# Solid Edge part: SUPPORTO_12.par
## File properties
Subject: SUPPORTO_12
Author: Francesco
Template: Normal.par
Last saved by: Francesco
Revision: 7
Application: Solid Edge
Material: Alluminio, 1060
Stile della faccia: Alluminio
Stile di riempimento: ANSI38(Alluminio)
Stile virtuale: Alluminio lucidato
Coef. of Thermal Exp: 0.0
Thermal Conductivity: 221.0
Specific Heat: 920.0
Modulus of Elasticity: 68947570000.0
Poisson's Ratio: 0.33
Yield Stress: 27579028.0
Ultimate Stress: 68947570.0
Elongation: 0.0
Tipo di contenuto documento: 0
Densità: 2712,000 kg/m^3
Precisione: 0,990
Document Number: KR0135
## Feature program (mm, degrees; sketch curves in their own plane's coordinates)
sketch for "unnamed Protrusion 1" #1 plane through (0, 0, 0) normal (0, -1, 0) x-axis (1, 0, 0)
  circle centre (1.4233, 0) radius 6
sketch for "unnamed Protrusion 1" #2 plane through (0, 0, 0) normal (0, -1, 0) x-axis (1, 0, 0)
  line (24.9233, 0) -> (24.9233, 4.3)
  line (24.9233, 4.3) -> (10.3349, 8.7655)
  line (9.3193, 15.5) -> (9.3193, 9.6904)
  line (1.4233, 15.5) -> (9.3193, 15.5)
  line (1.4233, 15.5) -> (-7.4883, 15.5)
  line (-7.4883, 8.7655) -> (-7.4883, 15.5)
  line (-22.0767, 4.3) -> (-7.4883, 8.7655)
  line (-22.0767, 4.3) -> (-22.0767, -4.3)
  line (-22.0767, -4.3) -> (-3.5087, -11.4859)
  arc centre (1.4233, 0) radius 12.5 from (6.3553, -11.4859) to (-3.5087, -11.4859) cw
  line (24.9233, -4.3) -> (6.3553, -11.4859)
  line (24.9233, 0) -> (24.9233, -4.3)
extrude "unnamed Protrusion 1" add finite 7.2 along +normal
sketch for "ExtrudedProtrusion_4" #1 plane through (1.4233, 0, 0) normal (0, 1, 0) x-axis (-0.956206, 0, 0.292694)
  circle centre (0, 0) radius 6
sketch for "ExtrudedProtrusion_4" #2 plane through (1.4233, 0, 0) normal (0, 1, 0) x-axis (-0.956206, 0, 0.292694)
  circle centre (0, 0) radius 12.5
extrude "ExtrudedProtrusion_4" add finite 6 along +normal
sketch for "Foro_13" plane through (9.3193, -3.6, 12.5952) normal (1, 0, 0) x-axis (0, 1, 0)
  hole centre (0, 0) bore radius 1.5
hole "Foro_13" diameter 3 through
fillet "Rotondo_3" radius 1
sketch for "ExtrudedCutout_4" plane through (1.4233, 6, 0) normal (0, 1, 0) x-axis (-1, 0, 0)
  line (0, 3.883) -> (0, 16.0651)
  line (0, 16.0651) -> (-0.5, 16.0651)
  line (-0.5, 16.0651) -> (-0.5, 3.883)
  line (-0.5, 3.883) -> (0, 3.883)
extrude "ExtrudedCutout_4" cut finite 66.4847 along -normal
sketch for "unnamed Cutout 1" plane through (1.4233, -7.2, 1.5) normal (0, -1, 0) x-axis (0.956206, 0, -0.292694)
  circle centre (-16.6213, -6.6849) radius 2.65
extrude "unnamed Cutout 1" cut finite 39.4874 along -normal
mirror "unnamed Mirror 1" of "unnamed Cutout 1"
pattern "unnamed Pattern 1"
chamfer "Smusso_1" setback 0.5
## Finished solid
Body 1: solid body, 35 faces, 85 edges, 48 vertices.
  Faces by surface: plane 18, cylinder 12, cone 4, torus 1
  Edges by curve: line 49, circle 35, intersection 1
Bounding box of the edges (mm; curved faces can reach further): 47.000 x 13.200 x 28.000, from (-22.0767, -7.2, -12.5) to (24.9233, 6, 15.5).
Cylindrical faces by radius (mm): R1 x6, R1.5 x2, R2.65 x2, R6 x1, R12.5 x1
Conical faces (half-angle, radius in mm at the cone's reference point): 45 deg R2.65 x2, 45 deg R3.15 x2
Toroidal faces (ring radius, tube radius in mm): R11.5 r1 x1
Planar faces by outward normal: +x 3, +y 5, +z 2, -x 3, -y 1, oblique 4
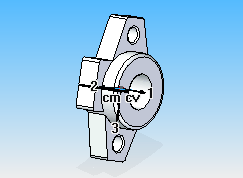
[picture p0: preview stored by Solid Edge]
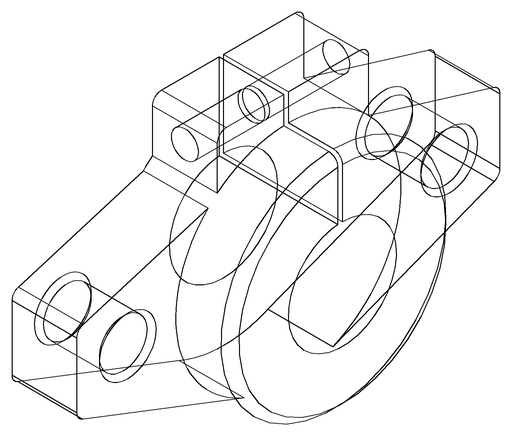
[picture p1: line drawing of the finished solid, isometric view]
